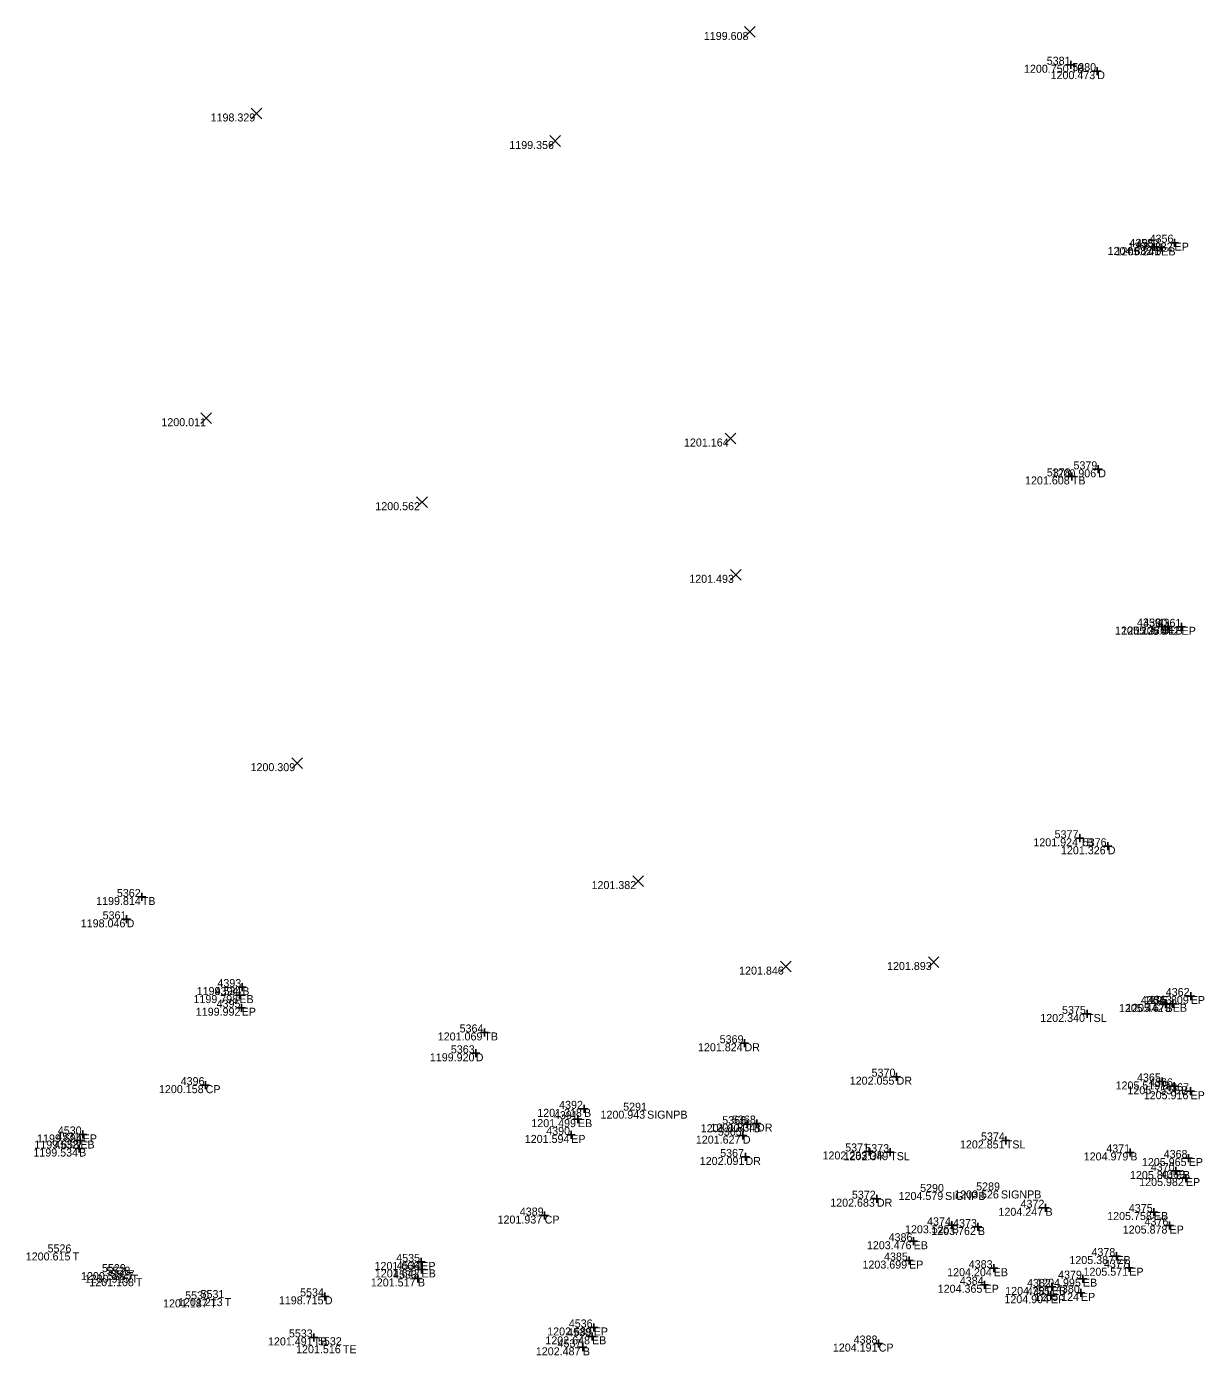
# Model space of a CAD drawing. Extents: x 2044997 to 2050342, y 455233 to 458054.
# Drawn here: x 2047474.9 to 2047622, y 457010.3 to 457176.4 of the extents above; entities that cross this region are included whole.
import ezdxf

# ---------------------------------------------------------------- set-up
doc = ezdxf.new("R2010")
doc.units = 0
for name, color, linetype in [('SV_X_Random_Point', 7, 'Continuous'), ('SV_X_Shot_Marker', 7, 'Continuous'), ('SV_X_Text_Comment', 7, 'Continuous'), ('SV_X_Text_Elevation', 7, 'Continuous'), ('SV_X_Text_Name', 7, 'Continuous')]:
    doc.layers.add(name, color=color, linetype=linetype)

msp = doc.modelspace()

# ---------------------------------------------------------------- linework, layer by layer
at = {"layer": 'SV_X_Random_Point'}
for p, q in [((2047564.57, 457175.1), (2047565.9, 457176.43)), ((2047564.57, 457176.43), (2047565.9, 457175.1)), ((2047502.93, 457164.9), (2047504.26, 457166.24)), ((2047502.93, 457166.24), (2047504.26, 457164.9)), ((2047540.27, 457161.46), (2047541.6, 457162.8)), ((2047540.27, 457162.8), (2047541.6, 457161.46)), ((2047496.67, 457126.82), (2047498.01, 457128.15)), ((2047496.67, 457128.15), (2047498.01, 457126.82)), ((2047562.16, 457124.28), (2047563.5, 457125.61)), ((2047562.16, 457125.61), (2047563.5, 457124.28)), ((2047523.62, 457116.31), (2047524.96, 457117.65)), ((2047523.62, 457117.65), (2047524.96, 457116.31)), ((2047562.84, 457107.23), (2047564.17, 457108.57)), ((2047562.84, 457108.57), (2047564.17, 457107.23)), ((2047508.02, 457083.7), (2047509.35, 457085.03)), ((2047508.02, 457085.03), (2047509.35, 457083.7)), ((2047550.64, 457068.95), (2047551.97, 457070.28)), ((2047550.64, 457070.28), (2047551.97, 457068.95)), ((2047569.09, 457058.26), (2047570.42, 457059.59)), ((2047569.09, 457059.59), (2047570.42, 457058.26)), ((2047587.55, 457058.83), (2047588.88, 457060.16)), ((2047587.55, 457060.16), (2047588.88, 457058.83))]:
    msp.add_line(p, q, dxfattribs=at)
at = {"layer": 'SV_X_Shot_Marker'}
for p, q in [((2047605.34, 457172.16), (2047605.34, 457171.16)), ((2047604.84, 457171.66), (2047605.84, 457171.66)), ((2047605.34, 457171.66), (2047605.34, 457171.66)), ((2047608.15, 457170.86), (2047609.15, 457170.86)), ((2047608.65, 457171.36), (2047608.65, 457170.36)), ((2047608.65, 457170.86), (2047608.65, 457170.86)), ((2047615.28, 457148.89), (2047616.28, 457148.89)), ((2047615.78, 457149.39), (2047615.78, 457148.39)), ((2047615.78, 457148.89), (2047615.78, 457148.89)), ((2047616.15, 457148.83), (2047617.15, 457148.83)), ((2047616.65, 457149.33), (2047616.65, 457148.33)), ((2047616.65, 457148.83), (2047616.65, 457148.83)), ((2047617.81, 457149.42), (2047618.81, 457149.42)), ((2047618.31, 457149.92), (2047618.31, 457148.92)), ((2047618.31, 457149.42), (2047618.31, 457149.42)), ((2047605.47, 457120.7), (2047605.47, 457119.7)), ((2047608.28, 457121.09), (2047609.28, 457121.09)), ((2047608.78, 457121.59), (2047608.78, 457120.59)), ((2047608.78, 457121.09), (2047608.78, 457121.09)), ((2047604.97, 457120.2), (2047605.97, 457120.2)), ((2047605.47, 457120.2), (2047605.47, 457120.2)), ((2047616.21, 457101.44), (2047617.21, 457101.44)), ((2047616.71, 457101.94), (2047616.71, 457100.94)), ((2047616.71, 457101.44), (2047616.71, 457101.44)), ((2047617.02, 457101.43), (2047618.02, 457101.43)), ((2047617.52, 457101.93), (2047617.52, 457100.93)), ((2047617.52, 457101.43), (2047617.52, 457101.43)), ((2047618.69, 457101.4), (2047619.69, 457101.4)), ((2047619.19, 457101.9), (2047619.19, 457100.9)), ((2047619.19, 457101.4), (2047619.19, 457101.4)), ((2047605.98, 457074.97), (2047606.98, 457074.97)), ((2047606.48, 457075.47), (2047606.48, 457074.47)), ((2047606.48, 457074.97), (2047606.48, 457074.97)), ((2047609.46, 457073.97), (2047610.46, 457073.97)), ((2047609.96, 457074.47), (2047609.96, 457073.47)), ((2047609.96, 457073.97), (2047609.96, 457073.97)), ((2047488.78, 457067.63), (2047489.78, 457067.63)), ((2047489.28, 457068.13), (2047489.28, 457067.13)), ((2047489.28, 457067.63), (2047489.28, 457067.63)), ((2047486.89, 457064.84), (2047487.89, 457064.84)), ((2047487.39, 457065.34), (2047487.39, 457064.34)), ((2047487.39, 457064.84), (2047487.39, 457064.84)), ((2047501.34, 457056.37), (2047502.34, 457056.37)), ((2047501.47, 457055.87), (2047501.47, 457054.87)), ((2047501.84, 457056.87), (2047501.84, 457055.87)), ((2047501.84, 457056.37), (2047501.84, 457056.37)), ((2047620.33, 457055.75), (2047620.33, 457054.75)), ((2047500.97, 457055.37), (2047501.97, 457055.37)), ((2047501.47, 457055.37), (2047501.47, 457055.37)), ((2047501.76, 457054.29), (2047501.76, 457053.29)), ((2047616.69, 457054.24), (2047617.69, 457054.24)), ((2047617.19, 457054.74), (2047617.19, 457053.74)), ((2047617.19, 457054.24), (2047617.19, 457054.24)), ((2047617.59, 457054.28), (2047618.59, 457054.28)), ((2047618.09, 457054.78), (2047618.09, 457053.78)), ((2047618.09, 457054.28), (2047618.09, 457054.28)), ((2047619.83, 457055.25), (2047620.83, 457055.25)), ((2047620.33, 457055.25), (2047620.33, 457055.25)), ((2047501.26, 457053.79), (2047502.26, 457053.79)), ((2047501.76, 457053.79), (2047501.76, 457053.79)), ((2047606.88, 457053.01), (2047607.88, 457053.01)), ((2047607.38, 457053.51), (2047607.38, 457052.51)), ((2047607.38, 457053.01), (2047607.38, 457053.01)), ((2047531.58, 457050.7), (2047532.58, 457050.7)), ((2047532.08, 457051.2), (2047532.08, 457050.2)), ((2047532.08, 457050.7), (2047532.08, 457050.7)), ((2047564.08, 457049.35), (2047565.08, 457049.35)), ((2047564.58, 457049.85), (2047564.58, 457048.85)), ((2047564.58, 457049.35), (2047564.58, 457049.35)), ((2047530.5, 457048.09), (2047531.5, 457048.09)), ((2047531, 457048.59), (2047531, 457047.59)), ((2047531, 457048.09), (2047531, 457048.09)), ((2047583.58, 457045.67), (2047583.58, 457044.67)), ((2047496.76, 457044.11), (2047497.76, 457044.11)), ((2047497.26, 457044.61), (2047497.26, 457043.61)), ((2047497.26, 457044.11), (2047497.26, 457044.11)), ((2047583.08, 457045.17), (2047584.08, 457045.17)), ((2047583.58, 457045.17), (2047583.58, 457045.17)), ((2047616.25, 457044.57), (2047617.25, 457044.57)), ((2047616.75, 457045.07), (2047616.75, 457044.07)), ((2047616.75, 457044.57), (2047616.75, 457044.57)), ((2047617.75, 457043.97), (2047618.75, 457043.97)), ((2047618.25, 457044.47), (2047618.25, 457043.47)), ((2047618.25, 457043.97), (2047618.25, 457043.97)), ((2047619.8, 457043.35), (2047620.8, 457043.35)), ((2047620.3, 457043.85), (2047620.3, 457042.85)), ((2047620.3, 457043.35), (2047620.3, 457043.35)), ((2047544.03, 457041.15), (2047545.03, 457041.15)), ((2047544.53, 457041.65), (2047544.53, 457040.65)), ((2047544.53, 457041.15), (2047544.53, 457041.15)), ((2047543.27, 457039.86), (2047544.27, 457039.86)), ((2047543.77, 457040.36), (2047543.77, 457039.36)), ((2047543.77, 457039.86), (2047543.77, 457039.86)), ((2047564.42, 457039.23), (2047565.42, 457039.23)), ((2047564.92, 457039.73), (2047564.92, 457038.73)), ((2047564.92, 457039.23), (2047564.92, 457039.23)), ((2047565.64, 457039.31), (2047566.64, 457039.31)), ((2047566.14, 457039.81), (2047566.14, 457038.81)), ((2047566.14, 457039.31), (2047566.14, 457039.31)), ((2047481.4, 457037.95), (2047482.4, 457037.95)), ((2047481.6, 457037.69), (2047481.6, 457036.69)), ((2047481.9, 457038.45), (2047481.9, 457037.45)), ((2047481.9, 457037.95), (2047481.9, 457037.95)), ((2047542.43, 457037.89), (2047543.43, 457037.89)), ((2047542.93, 457038.39), (2047542.93, 457037.39)), ((2047542.93, 457037.89), (2047542.93, 457037.89)), ((2047563.88, 457037.8), (2047564.88, 457037.8)), ((2047564.38, 457038.3), (2047564.38, 457037.3)), ((2047564.38, 457037.8), (2047564.38, 457037.8)), ((2047597.22, 457037.7), (2047597.22, 457036.7)), ((2047480.95, 457036.19), (2047481.95, 457036.19)), ((2047481.1, 457037.19), (2047482.1, 457037.19)), ((2047481.45, 457036.69), (2047481.45, 457035.69)), ((2047481.45, 457036.19), (2047481.45, 457036.19)), ((2047481.6, 457037.19), (2047481.6, 457037.19)), ((2047564.7, 457035.63), (2047564.7, 457034.63)), ((2047579.66, 457035.82), (2047580.66, 457035.82)), ((2047580.16, 457036.32), (2047580.16, 457035.32)), ((2047580.16, 457035.82), (2047580.16, 457035.82)), ((2047582.28, 457035.73), (2047583.28, 457035.73)), ((2047582.78, 457036.23), (2047582.78, 457035.23)), ((2047582.78, 457035.73), (2047582.78, 457035.73)), ((2047596.72, 457037.2), (2047597.72, 457037.2)), ((2047597.22, 457037.2), (2047597.22, 457037.2)), ((2047612.28, 457035.7), (2047613.28, 457035.7)), ((2047612.78, 457036.2), (2047612.78, 457035.2)), ((2047612.78, 457035.7), (2047612.78, 457035.7)), ((2047564.2, 457035.13), (2047565.2, 457035.13)), ((2047564.7, 457035.13), (2047564.7, 457035.13)), ((2047619.57, 457035), (2047620.57, 457035)), ((2047620.07, 457035.5), (2047620.07, 457034.5)), ((2047620.07, 457035), (2047620.07, 457035)), ((2047617.96, 457033.38), (2047618.96, 457033.38)), ((2047618.46, 457033.88), (2047618.46, 457032.88)), ((2047618.46, 457033.38), (2047618.46, 457033.38)), ((2047619.22, 457032.5), (2047620.22, 457032.5)), ((2047619.72, 457033), (2047619.72, 457032)), ((2047619.72, 457032.5), (2047619.72, 457032.5)), ((2047580.62, 457029.92), (2047581.62, 457029.92)), ((2047581.12, 457030.42), (2047581.12, 457029.42)), ((2047581.12, 457029.92), (2047581.12, 457029.92)), ((2047602.19, 457029.28), (2047602.19, 457028.28)), ((2047539.11, 457027.81), (2047540.11, 457027.81)), ((2047539.61, 457028.31), (2047539.61, 457027.31)), ((2047539.61, 457027.81), (2047539.61, 457027.81)), ((2047601.69, 457028.78), (2047602.69, 457028.78)), ((2047602.19, 457028.78), (2047602.19, 457028.78)), ((2047615.23, 457028.25), (2047616.23, 457028.25)), ((2047615.73, 457028.75), (2047615.73, 457027.75)), ((2047615.73, 457028.25), (2047615.73, 457028.25)), ((2047589.98, 457026.59), (2047590.98, 457026.59)), ((2047590.48, 457027.09), (2047590.48, 457026.09)), ((2047590.48, 457026.59), (2047590.48, 457026.59)), ((2047593.24, 457026.38), (2047594.24, 457026.38)), ((2047593.74, 457026.88), (2047593.74, 457025.88)), ((2047593.74, 457026.38), (2047593.74, 457026.38)), ((2047617.18, 457026.56), (2047618.18, 457026.56)), ((2047617.68, 457027.06), (2047617.68, 457026.06)), ((2047617.68, 457026.56), (2047617.68, 457026.56)), ((2047585.21, 457024.6), (2047586.21, 457024.6)), ((2047585.71, 457025.1), (2047585.71, 457024.1)), ((2047585.71, 457024.6), (2047585.71, 457024.6)), ((2047524.2, 457022.51), (2047524.2, 457021.51)), ((2047585.14, 457022.68), (2047585.14, 457021.68)), ((2047610.55, 457022.75), (2047611.55, 457022.75)), ((2047611.05, 457023.25), (2047611.05, 457022.25)), ((2047611.05, 457022.75), (2047611.05, 457022.75)), ((2047523.7, 457022.01), (2047524.7, 457022.01)), ((2047523.73, 457021.08), (2047524.73, 457021.08)), ((2047524.2, 457022.01), (2047524.2, 457022.01)), ((2047524.23, 457021.58), (2047524.23, 457020.58)), ((2047524.23, 457021.08), (2047524.23, 457021.08)), ((2047584.64, 457022.18), (2047585.64, 457022.18)), ((2047585.14, 457022.18), (2047585.14, 457022.18)), ((2047595.21, 457021.23), (2047596.21, 457021.23)), ((2047595.71, 457021.73), (2047595.71, 457020.73)), ((2047595.71, 457021.23), (2047595.71, 457021.23)), ((2047612.15, 457021.29), (2047613.15, 457021.29)), ((2047612.65, 457021.79), (2047612.65, 457020.79)), ((2047612.65, 457021.29), (2047612.65, 457021.29)), ((2047523.28, 457019.95), (2047524.28, 457019.95)), ((2047523.78, 457020.45), (2047523.78, 457019.45)), ((2047523.78, 457019.95), (2047523.78, 457019.95)), ((2047594.07, 457019.16), (2047595.07, 457019.16)), ((2047594.57, 457019.66), (2047594.57, 457018.66)), ((2047594.57, 457019.16), (2047594.57, 457019.16)), ((2047602.99, 457019.39), (2047602.99, 457018.39)), ((2047606.36, 457019.92), (2047607.36, 457019.92)), ((2047606.86, 457020.42), (2047606.86, 457019.42)), ((2047606.86, 457019.92), (2047606.86, 457019.92)), ((2047511.65, 457017.71), (2047512.65, 457017.71)), ((2047512.15, 457018.21), (2047512.15, 457017.21)), ((2047512.15, 457017.71), (2047512.15, 457017.71)), ((2047602.36, 457017.85), (2047603.36, 457017.85)), ((2047602.49, 457018.89), (2047603.49, 457018.89)), ((2047602.86, 457018.35), (2047602.86, 457017.35)), ((2047602.86, 457017.85), (2047602.86, 457017.85)), ((2047602.99, 457018.89), (2047602.99, 457018.89)), ((2047606.11, 457018.15), (2047607.11, 457018.15)), ((2047606.61, 457018.65), (2047606.61, 457017.65)), ((2047606.61, 457018.15), (2047606.61, 457018.15)), ((2047545.75, 457014.32), (2047545.75, 457013.32)), ((2047510.26, 457012.58), (2047511.26, 457012.58)), ((2047510.76, 457013.08), (2047510.76, 457012.08)), ((2047510.76, 457012.58), (2047510.76, 457012.58)), ((2047545.03, 457012.71), (2047546.03, 457012.71)), ((2047545.25, 457013.82), (2047546.25, 457013.82)), ((2047545.53, 457013.21), (2047545.53, 457012.21)), ((2047545.53, 457012.71), (2047545.53, 457012.71)), ((2047545.75, 457013.82), (2047545.75, 457013.82)), ((2047543.89, 457011.34), (2047544.89, 457011.34)), ((2047544.39, 457011.84), (2047544.39, 457010.84)), ((2047544.39, 457011.34), (2047544.39, 457011.34)), ((2047580.84, 457011.81), (2047581.84, 457011.81)), ((2047581.34, 457012.31), (2047581.34, 457011.31)), ((2047581.34, 457011.81), (2047581.34, 457011.81))]:
    msp.add_line(p, q, dxfattribs=at)

# ---------------------------------------------------------------- texts
at = {"layer": 'SV_X_Text_Comment'}
for s, p in [('TB', (2047605.34, 457170.66)), ('D', (2047608.65, 457169.86)), ('B', (2047615.78, 457147.89)), ('EB', (2047616.65, 457147.83)), ('EP', (2047618.31, 457148.42)), ('D', (2047608.78, 457120.09)), ('TB', (2047605.47, 457119.2)), ('B', (2047616.71, 457100.44)), ('EB', (2047617.52, 457100.43)), ('EP', (2047619.19, 457100.4)), ('TB', (2047606.48, 457073.97)), ('D', (2047609.96, 457072.97)), ('TB', (2047489.28, 457066.63)), ('D', (2047487.39, 457063.84)), ('B', (2047501.84, 457055.37)), ('EB', (2047501.47, 457054.37)), ('B', (2047617.19, 457053.24)), ('EB', (2047618.09, 457053.28)), ('EP', (2047620.33, 457054.25)), ('EP', (2047501.76, 457052.79)), ('TSL', (2047607.38, 457052.01)), ('TB', (2047532.08, 457049.7)), ('DR', (2047564.58, 457048.35)), ('D', (2047531, 457047.09)), ('CP', (2047497.26, 457043.11)), ('DR', (2047583.58, 457044.17)), ('B', (2047616.75, 457043.57)), ('EB', (2047618.25, 457042.97)), ('EP', (2047620.3, 457042.35)), ('B', (2047544.53, 457040.15)), ('SIGNPB', (2047552.41, 457039.92)), ('EB', (2047543.77, 457038.86)), ('TB', (2047564.92, 457038.23)), ('DR', (2047566.14, 457038.31)), ('EP', (2047481.9, 457036.95)), ('EP', (2047542.93, 457036.89)), ('D', (2047564.38, 457036.8)), ('B', (2047481.45, 457035.19)), ('EB', (2047481.6, 457036.19)), ('DR', (2047580.16, 457034.82)), ('TSL', (2047582.78, 457034.73)), ('TSL', (2047597.22, 457036.2)), ('B', (2047612.78, 457034.7)), ('DR', (2047564.7, 457034.13)), ('EP', (2047620.07, 457034)), ('EB', (2047618.46, 457032.38)), ('EP', (2047619.72, 457031.5)), ('SIGNPB', (2047589.64, 457029.76)), ('SIGNPB', (2047596.62, 457029.95)), ('DR', (2047581.12, 457028.92)), ('CP', (2047539.61, 457026.81)), ('B', (2047602.19, 457027.78)), ('EB', (2047615.73, 457027.25)), ('B', (2047590.48, 457025.59)), ('B', (2047593.74, 457025.38)), ('EP', (2047617.68, 457025.56)), ('EB', (2047585.71, 457023.6)), ('T', (2047480.64, 457022.2)), ('EB', (2047611.05, 457021.75)), ('T', (2047487.41, 457019.74)), ('EP', (2047524.2, 457021.01)), ('EB', (2047524.23, 457020.08)), ('EP', (2047585.14, 457021.18)), ('EB', (2047595.71, 457020.23)), ('EP', (2047612.65, 457020.29)), ('T', (2047488.01, 457019.41)), ('T', (2047488.56, 457018.98)), ('B', (2047523.78, 457018.95)), ('EP', (2047594.57, 457018.16)), ('EB', (2047606.86, 457018.92)), ('T', (2047499.63, 457016.49)), ('D', (2047512.15, 457016.71)), ('EP', (2047602.86, 457016.85)), ('EB', (2047602.99, 457017.89)), ('EP', (2047606.61, 457017.15)), ('T', (2047497.82, 457016.33)), ('TB', (2047510.76, 457011.58)), ('EB', (2047545.53, 457011.71)), ('EP', (2047545.75, 457012.82)), ('TE', (2047514.4, 457010.6)), ('B', (2047544.39, 457010.34)), ('CP', (2047581.34, 457010.81))]:
    msp.add_text(s, height=1, dxfattribs=at).set_placement(p)
at = {"layer": 'SV_X_Text_Elevation'}
for s, p in [('1199.608', (2047559.5, 457174.76)), ('1200.750', (2047599.5, 457170.66)), ('1200.473', (2047602.82, 457169.86)), ('1198.329', (2047497.88, 457164.57)), ('1199.356', (2047535.2, 457161.13)), ('1204.882', (2047609.95, 457147.89)), ('1205.241', (2047610.94, 457147.83)), ('1205.282', (2047612.48, 457148.42)), ('1200.011', (2047491.73, 457126.48)), ('1201.164', (2047557.02, 457123.94)), ('1200.906', (2047602.94, 457120.09)), ('1201.608', (2047599.63, 457119.2)), ('1200.562', (2047518.46, 457115.98)), ('1201.493', (2047557.68, 457106.9)), ('1205.126', (2047610.87, 457100.44)), ('1205.370', (2047611.68, 457100.43)), ('1205.442', (2047613.35, 457100.4)), ('1200.309', (2047502.87, 457083.36)), ('1201.924', (2047600.67, 457073.97)), ('1201.326', (2047604.12, 457072.97)), ('1201.382', (2047545.47, 457068.62)), ('1199.814', (2047483.58, 457066.63)), ('1198.046', (2047481.66, 457063.84)), ('1201.846', (2047563.91, 457057.93)), ('1201.893', (2047582.39, 457058.5)), ('1199.534', (2047496.14, 457055.37)), ('1199.798', (2047495.74, 457054.37)), ('1205.442', (2047611.36, 457053.24)), ('1205.673', (2047612.26, 457053.28)), ('1205.809', (2047614.51, 457054.25)), ('1199.992', (2047496.03, 457052.79)), ('1202.340', (2047601.54, 457052.01)), ('1201.069', (2047526.26, 457049.7)), ('1201.824', (2047558.77, 457048.35)), ('1199.920', (2047525.27, 457047.09)), ('1200.158', (2047491.43, 457043.11)), ('1202.055', (2047577.73, 457044.17)), ('1205.519', (2047610.94, 457043.57)), ('1205.753', (2047612.42, 457042.97)), ('1205.916', (2047614.46, 457042.35)), ('1201.318', (2047538.69, 457040.15)), ('1200.943', (2047546.59, 457039.92)), ('1201.499', (2047537.95, 457038.86)), ('1201.804', (2047559.11, 457038.23)), ('1201.834', (2047560.33, 457038.31)), ('1199.694', (2047476.2, 457036.95)), ('1201.594', (2047537.13, 457036.89)), ('1201.627', (2047558.5, 457036.8)), ('1199.534', (2047475.74, 457035.19)), ('1199.658', (2047475.86, 457036.19)), ('1202.233', (2047574.33, 457034.82)), ('1202.349', (2047576.96, 457034.73)), ('1202.851', (2047591.5, 457036.2)), ('1204.979', (2047606.96, 457034.7)), ('1202.091', (2047558.99, 457034.13)), ('1205.965', (2047614.23, 457034)), ('1205.801', (2047612.74, 457032.38)), ('1205.982', (2047613.89, 457031.5)), ('1204.579', (2047583.83, 457029.76)), ('1203.526', (2047590.78, 457029.95)), ('1202.683', (2047575.29, 457028.92)), ('1201.937', (2047533.73, 457026.81)), ('1204.247', (2047596.31, 457027.78)), ('1205.758', (2047609.89, 457027.25)), ('1203.525', (2047584.63, 457025.59)), ('1203.762', (2047587.91, 457025.38)), ('1205.878', (2047611.84, 457025.56)), ('1203.476', (2047579.87, 457023.6)), ('1200.615', (2047474.79, 457022.2)), ('1205.387', (2047605.17, 457021.75)), ('1200.581', (2047481.69, 457019.74)), ('1201.666', (2047518.36, 457021.01)), ('1201.642', (2047518.4, 457020.08)), ('1203.699', (2047579.32, 457021.18)), ('1204.204', (2047589.9, 457020.23)), ('1205.571', (2047606.93, 457020.29)), ('1200.915', (2047482.16, 457019.41)), ('1201.108', (2047482.72, 457018.98)), ('1201.517', (2047517.9, 457018.95)), ('1204.365', (2047588.72, 457018.16)), ('1204.995', (2047601.02, 457018.92)), ('1201.187', (2047491.94, 457016.33)), ('1201.213', (2047493.81, 457016.49)), ('1198.715', (2047506.41, 457016.71)), ('1204.904', (2047597.05, 457016.85)), ('1204.755', (2047597.15, 457017.89)), ('1205.124', (2047600.8, 457017.15)), ('1201.491', (2047505.05, 457011.58)), ('1202.648', (2047539.7, 457011.71)), ('1202.689', (2047539.93, 457012.82)), ('1201.516', (2047508.56, 457010.6)), ('1202.487', (2047538.51, 457010.34)), ('1204.191', (2047575.62, 457010.81))]:
    msp.add_text(s, height=1, dxfattribs=at).set_placement(p)
at = {"layer": 'SV_X_Text_Name'}
for s, p in [('5381', (2047602.34, 457171.66)), ('5380', (2047605.53, 457170.86)), ('4356', (2047615.19, 457149.42)), ('4358', (2047612.66, 457148.89)), ('4357', (2047613.49, 457148.83)), ('5379', (2047605.68, 457121.09)), ('5378', (2047602.35, 457120.2)), ('4359', (2047613.61, 457101.44)), ('4360', (2047614.4, 457101.43)), ('4361', (2047616.19, 457101.4)), ('5377', (2047603.32, 457074.97)), ('5376', (2047606.84, 457073.97)), ('5362', (2047486.17, 457067.63)), ('5361', (2047484.39, 457064.84)), ('4393', (2047498.73, 457056.37)), ('4394', (2047498.38, 457055.37)), ('4362', (2047617.21, 457055.25)), ('4395', (2047498.63, 457053.79)), ('5375', (2047604.25, 457053.01)), ('4364', (2047614.1, 457054.24)), ('4363', (2047614.98, 457054.28)), ('5364', (2047528.99, 457050.7)), ('5363', (2047527.89, 457048.09)), ('5369', (2047561.48, 457049.35)), ('5370', (2047580.46, 457045.17)), ('4365', (2047613.62, 457044.57)), ('4396', (2047494.14, 457044.11)), ('4366', (2047615.12, 457043.97)), ('4367', (2047617.14, 457043.35)), ('4391', (2047540.77, 457039.86)), ('4392', (2047541.42, 457041.15)), ('5291', (2047549.42, 457040.92)), ('4530', (2047478.79, 457037.95)), ('5366', (2047561.8, 457039.23)), ('5368', (2047563.02, 457039.31)), ('4531', (2047478.6, 457037.19)), ('4390', (2047539.81, 457037.89)), ('5365', (2047561.25, 457037.8)), ('5374', (2047594.13, 457037.2)), ('4532', (2047478.33, 457036.19)), ('5367', (2047561.54, 457035.13)), ('5371', (2047577.16, 457035.82)), ('5373', (2047579.67, 457035.73)), ('4371', (2047609.78, 457035.7)), ('4368', (2047616.95, 457035)), ('4370', (2047615.34, 457033.38)), ('4369', (2047616.62, 457032.5)), ('5372', (2047578, 457029.92)), ('5290', (2047586.52, 457030.76)), ('5289', (2047593.52, 457030.95)), ('4372', (2047599.07, 457028.78)), ('4375', (2047612.6, 457028.25)), ('4389', (2047536.51, 457027.81)), ('4374', (2047587.39, 457026.59)), ('4373', (2047590.64, 457026.38)), ('4376', (2047614.56, 457026.56)), ('5526', (2047477.51, 457023.2)), ('4386', (2047582.59, 457024.6)), ('4535', (2047521.07, 457022.01)), ('4385', (2047582.01, 457022.18)), ('4378', (2047607.93, 457022.75)), ('5529', (2047484.31, 457020.74)), ('5528', (2047484.89, 457020.41)), ('5527', (2047485.4, 457019.98)), ('4533', (2047520.68, 457019.95)), ('4534', (2047521.14, 457021.08)), ('4383', (2047592.6, 457021.23)), ('4379', (2047603.76, 457019.92)), ('4377', (2047609.49, 457021.29)), ('4384', (2047591.48, 457019.16)), ('4382', (2047599.88, 457018.89)), ('4380', (2047603.49, 457018.15)), ('5530', (2047494.7, 457017.33)), ('5531', (2047496.63, 457017.49)), ('5534', (2047509.06, 457017.71)), ('4381', (2047599.86, 457017.85)), ('4536', (2047542.63, 457013.82)), ('5533', (2047507.66, 457012.58)), ('5532', (2047511.29, 457011.6)), ('4538', (2047542.42, 457012.71)), ('4388', (2047578.22, 457011.81)), ('4537', (2047541.22, 457011.34))]:
    msp.add_text(s, height=1, dxfattribs=at).set_placement(p)

doc.saveas('drawing.dxf')
